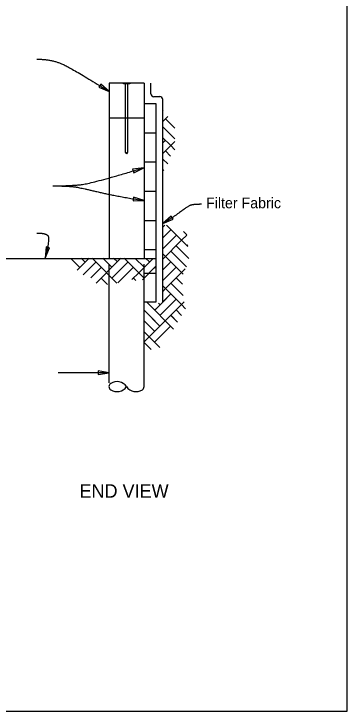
# Model space of a CAD drawing. Extents: x 10624 to 10731, y 76456 to 76513.
# Drawn here: x 10676.79 to 10686.28, y 76469.69 to 76489.57 of the extents above; entities that cross this region are included whole.
import ezdxf

# ---------------------------------------------------------------- set-up
doc = ezdxf.new("R2010")
doc.units = 0
for name, color, linetype in [('ActivePts-ConstElements', 7, 'Continuous'), ('Dimension', 7, 'Continuous'), ('GroundLines', 7, 'Continuous'), ('Miscellaneous', 7, 'Continuous'), ('Patterning', 7, 'Continuous'), ('SteelMisc', 7, 'Continuous'), ('SteelMisc_h', 7, 'Continuous'), ('TextStructures', 7, 'Continuous'), ('Wood', 7, 'Continuous'), ('Wood_h', 7, 'Continuous')]:
    doc.layers.add(name, color=color, linetype=linetype)

msp = doc.modelspace()

# ---------------------------------------------------------------- linework, layer by layer
at = {"layer": 'ActivePts-ConstElements'}
msp.add_lwpolyline([(10624.7, 76469.694), (10686.276, 76469.694), (10686.276, 76508.613), (10624.7, 76508.613)], close=True, dxfattribs=at)
at = {"layer": 'Dimension'}
msp.add_line((10679.5, 76479.339), (10678.045, 76479.339), dxfattribs=at)
for points in [[(10679.5, 76487.354), (10679.264, 76487.565), (10679.208, 76487.476)], [(10680.484, 76485.183), (10680.169, 76485.142), (10680.201, 76485.041)], [(10680.499, 76484.246), (10680.198, 76484.347), (10680.182, 76484.243)], [(10681.031, 76483.593), (10681.324, 76483.712), (10681.269, 76483.802)], [(10677.679, 76482.609), (10677.805, 76482.9), (10677.702, 76482.925)], [(10679.5, 76479.339), (10679.188, 76479.392), (10679.188, 76479.286)]]:
    msp.add_lwpolyline(points, close=True, dxfattribs=at)
msp.add_open_spline([(10677.442, 76483.32), (10677.726, 76483.32), (10677.808, 76483.134), (10677.679, 76482.609)], degree=2, dxfattribs=at)
at = {"layer": 'GroundLines'}
msp.add_line((10676.348, 76482.598), (10680.498, 76482.598), dxfattribs=at)
at = {"layer": 'Miscellaneous'}
for p, q in [((10680.689, 76487.292), (10680.689, 76487.598)), ((10680.772, 76487.209), (10680.943, 76487.209)), ((10681.026, 76481.348), (10681.026, 76487.126))]:
    msp.add_line(p, q, dxfattribs=at)
for centre, start, end in [((10680.772, 76487.292), 180, 270), ((10680.943, 76487.126), 0, 90)]:
    msp.add_arc(centre, 0.0833, start, end, dxfattribs=at)
at = {"layer": 'Patterning'}
for p, q in [((10681.03, 76486.805), (10681.015, 76486.79)), ((10681.03, 76486.805), (10681.015, 76486.79)), ((10681.03, 76486.805), (10681.015, 76486.79)), ((10681.17, 76486.646), (10681.018, 76486.494)), ((10681.17, 76486.646), (10681.018, 76486.494)), ((10681.17, 76486.646), (10681.018, 76486.494)), ((10681.104, 76486.58), (10681.371, 76486.313)), ((10681.104, 76486.58), (10681.371, 76486.313)), ((10681.104, 76486.58), (10681.371, 76486.313)), ((10681.02, 76486.359), (10681.371, 76486.008)), ((10681.02, 76486.359), (10681.371, 76486.008)), ((10681.02, 76486.359), (10681.371, 76486.008)), ((10681.254, 76485.813), (10681.024, 76486.043)), ((10681.254, 76485.813), (10681.024, 76486.043)), ((10681.254, 76485.813), (10681.024, 76486.043)), ((10681.101, 76485.966), (10681.025, 76485.89)), ((10681.101, 76485.966), (10681.025, 76485.89)), ((10681.101, 76485.966), (10681.025, 76485.89)), ((10681.254, 76485.813), (10681.029, 76485.588)), ((10681.254, 76485.813), (10681.029, 76485.588)), ((10681.254, 76485.813), (10681.029, 76485.588)), ((10681.371, 76485.93), (10681.254, 76485.813)), ((10681.371, 76485.93), (10681.254, 76485.813)), ((10681.371, 76485.93), (10681.254, 76485.813)), ((10681.371, 76485.696), (10681.254, 76485.813)), ((10681.371, 76485.696), (10681.254, 76485.813)), ((10681.371, 76485.696), (10681.254, 76485.813)), ((10681.251, 76485.517), (10681.104, 76485.663)), ((10681.251, 76485.517), (10681.104, 76485.663)), ((10681.251, 76485.517), (10681.104, 76485.663)), ((10681.171, 76485.291), (10681.031, 76485.431)), ((10681.171, 76485.291), (10681.031, 76485.431)), ((10681.171, 76485.291), (10681.031, 76485.431)), ((10681.054, 76485.102), (10681.034, 76485.122)), ((10681.054, 76485.102), (10681.034, 76485.122)), ((10681.054, 76485.102), (10681.034, 76485.122)), ((10681.085, 76483.545), (10681.025, 76483.485)), ((10681.085, 76483.545), (10681.025, 76483.485)), ((10681.085, 76483.545), (10681.025, 76483.485)), ((10681.261, 76483.416), (10681.025, 76483.18)), ((10681.261, 76483.416), (10681.025, 76483.18)), ((10681.261, 76483.416), (10681.025, 76483.18)), ((10681.565, 76483.115), (10681.135, 76483.545)), ((10681.565, 76483.115), (10681.135, 76483.545)), ((10681.565, 76483.115), (10681.135, 76483.545)), ((10681.414, 76483.263), (10681.025, 76482.875)), ((10681.414, 76483.263), (10681.025, 76482.875)), ((10681.414, 76483.263), (10681.025, 76482.875)), ((10681.715, 76483.265), (10681.565, 76483.115)), ((10681.715, 76483.265), (10681.565, 76483.115)), ((10681.715, 76483.265), (10681.565, 76483.115)), ((10681.714, 76483.271), (10681.622, 76483.363)), ((10681.714, 76483.271), (10681.622, 76483.363)), ((10681.714, 76483.271), (10681.622, 76483.363)), ((10681.563, 76483.114), (10681.025, 76482.576)), ((10681.563, 76483.114), (10681.025, 76482.576)), ((10681.563, 76483.114), (10681.025, 76482.576)), ((10681.563, 76483.114), (10681.744, 76482.933)), ((10681.563, 76483.114), (10681.744, 76482.933)), ((10681.563, 76483.114), (10681.744, 76482.933)), ((10681.74, 76482.984), (10681.718, 76482.963)), ((10681.74, 76482.984), (10681.718, 76482.963)), ((10681.74, 76482.984), (10681.718, 76482.963)), ((10681.258, 76482.808), (10681.703, 76482.362)), ((10681.258, 76482.808), (10681.703, 76482.362)), ((10681.258, 76482.808), (10681.703, 76482.362)), ((10681.41, 76482.961), (10681.773, 76482.598)), ((10681.41, 76482.961), (10681.773, 76482.598)), ((10681.41, 76482.961), (10681.773, 76482.598)), ((10678.409, 76482.597), (10678.665, 76482.34)), ((10678.409, 76482.597), (10678.665, 76482.34)), ((10678.409, 76482.597), (10678.665, 76482.34)), ((10678.93, 76482.605), (10678.59, 76482.265)), ((10678.93, 76482.605), (10678.59, 76482.265)), ((10678.93, 76482.605), (10678.59, 76482.265)), ((10678.705, 76482.606), (10678.818, 76482.493)), ((10678.705, 76482.606), (10678.818, 76482.493)), ((10678.705, 76482.606), (10678.818, 76482.493)), ((10679.428, 76482.192), (10679.015, 76482.605)), ((10679.428, 76482.192), (10679.015, 76482.605)), ((10679.428, 76482.192), (10679.015, 76482.605)), ((10679.58, 76482.345), (10679.322, 76482.603)), ((10679.58, 76482.345), (10679.322, 76482.603)), ((10679.58, 76482.345), (10679.322, 76482.603)), ((10679.837, 76482.601), (10679.428, 76482.192)), ((10679.837, 76482.601), (10679.428, 76482.192)), ((10679.837, 76482.601), (10679.428, 76482.192)), ((10679.733, 76482.498), (10679.628, 76482.602)), ((10679.733, 76482.498), (10679.628, 76482.602)), ((10679.733, 76482.498), (10679.628, 76482.602)), ((10680.341, 76482.189), (10679.929, 76482.601)), ((10680.341, 76482.189), (10679.929, 76482.601)), ((10680.341, 76482.189), (10679.929, 76482.601)), ((10680.242, 76482.6), (10680.497, 76482.345)), ((10680.242, 76482.6), (10680.497, 76482.345)), ((10680.242, 76482.6), (10680.497, 76482.345)), ((10680.75, 76482.598), (10680.341, 76482.189)), ((10680.75, 76482.598), (10680.341, 76482.189)), ((10680.75, 76482.598), (10680.341, 76482.189)), ((10680.498, 76482.598), (10680.832, 76482.598)), ((10680.548, 76482.599), (10680.649, 76482.498)), ((10680.548, 76482.599), (10680.649, 76482.498)), ((10680.548, 76482.599), (10680.649, 76482.498)), ((10681.56, 76482.194), (10681.025, 76482.729)), ((10681.56, 76482.194), (10681.025, 76482.729)), ((10681.56, 76482.194), (10681.025, 76482.729)), ((10679.123, 76482.493), (10678.762, 76482.131)), ((10679.123, 76482.493), (10678.762, 76482.131)), ((10679.123, 76482.493), (10678.762, 76482.131)), ((10680.035, 76482.495), (10679.58, 76482.039)), ((10680.035, 76482.495), (10679.58, 76482.039)), ((10680.035, 76482.495), (10679.58, 76482.039)), ((10681.255, 76482.5), (10681.025, 76482.27)), ((10681.255, 76482.5), (10681.025, 76482.27)), ((10681.255, 76482.5), (10681.025, 76482.27)), ((10679.276, 76482.34), (10678.981, 76482.044)), ((10679.276, 76482.34), (10678.981, 76482.044)), ((10679.276, 76482.34), (10678.981, 76482.044)), ((10679.426, 76482.19), (10679.127, 76481.892)), ((10679.426, 76482.19), (10679.127, 76481.892)), ((10679.426, 76482.19), (10679.127, 76481.892)), ((10679.426, 76482.19), (10679.723, 76481.893)), ((10679.426, 76482.19), (10679.723, 76481.893)), ((10679.426, 76482.19), (10679.723, 76481.893)), ((10680.188, 76482.342), (10679.744, 76481.898)), ((10680.188, 76482.342), (10679.744, 76481.898)), ((10680.188, 76482.342), (10679.744, 76481.898)), ((10680.341, 76482.189), (10680.144, 76481.992)), ((10680.341, 76482.189), (10680.144, 76481.992)), ((10680.341, 76482.189), (10680.144, 76481.992)), ((10680.493, 76482.037), (10680.341, 76482.189)), ((10680.417, 76482.113), (10680.341, 76482.189)), ((10680.417, 76482.113), (10680.341, 76482.189)), ((10680.832, 76482.374), (10680.447, 76481.99)), ((10680.832, 76482.374), (10680.779, 76482.322)), ((10680.832, 76482.374), (10680.779, 76482.322)), ((10681.407, 76482.347), (10681.026, 76481.965)), ((10681.407, 76482.347), (10681.026, 76481.965)), ((10681.407, 76482.347), (10681.026, 76481.965)), ((10681.56, 76482.194), (10681.105, 76481.739)), ((10681.56, 76482.194), (10681.105, 76481.739)), ((10681.56, 76482.194), (10681.105, 76481.739)), ((10681.667, 76482.301), (10681.56, 76482.194)), ((10681.667, 76482.301), (10681.56, 76482.194)), ((10681.667, 76482.301), (10681.56, 76482.194)), ((10681.609, 76482.146), (10681.56, 76482.194)), ((10681.609, 76482.146), (10681.56, 76482.194)), ((10681.609, 76482.146), (10681.56, 76482.194)), ((10679.273, 76482.038), (10679.455, 76481.856)), ((10679.273, 76482.038), (10679.455, 76481.856)), ((10679.273, 76482.038), (10679.455, 76481.856)), ((10680.259, 76481.972), (10680.191, 76482.039)), ((10680.22, 76482.01), (10680.191, 76482.039)), ((10680.22, 76482.01), (10680.191, 76482.039)), ((10681.591, 76481.863), (10681.411, 76482.044)), ((10681.591, 76481.863), (10681.411, 76482.044)), ((10681.591, 76481.863), (10681.411, 76482.044)), ((10681.026, 76481.815), (10681.103, 76481.737)), ((10681.026, 76481.815), (10681.103, 76481.737)), ((10681.026, 76481.815), (10681.103, 76481.737)), ((10681.609, 76481.54), (10681.258, 76481.892)), ((10681.609, 76481.54), (10681.258, 76481.892)), ((10681.609, 76481.54), (10681.258, 76481.892)), ((10681.103, 76481.737), (10681.026, 76481.659)), ((10681.103, 76481.737), (10681.026, 76481.659)), ((10681.103, 76481.737), (10681.026, 76481.659)), ((10681.56, 76481.284), (10681.105, 76481.739)), ((10681.56, 76481.284), (10681.105, 76481.739)), ((10681.56, 76481.284), (10681.105, 76481.739)), ((10681.256, 76481.584), (10680.808, 76481.136)), ((10681.409, 76481.432), (10680.948, 76480.97)), ((10681.256, 76481.584), (10681.026, 76481.354)), ((10681.256, 76481.584), (10681.026, 76481.354)), ((10681.334, 76480.584), (10680.58, 76481.338)), ((10681.558, 76481.282), (10680.637, 76480.36)), ((10680.905, 76481.324), (10680.948, 76481.281)), ((10681.558, 76481.282), (10681.678, 76481.163)), ((10681.558, 76481.282), (10681.678, 76481.163)), ((10681.558, 76481.282), (10681.678, 76481.163)), ((10681.641, 76481.364), (10681.56, 76481.284)), ((10681.641, 76481.364), (10681.56, 76481.284)), ((10681.641, 76481.364), (10681.56, 76481.284)), ((10680.948, 76480.671), (10680.51, 76481.109)), ((10680.824, 76481.153), (10680.795, 76481.123)), ((10680.824, 76481.153), (10680.795, 76481.123)), ((10680.824, 76481.153), (10680.795, 76481.123)), ((10681.406, 76481.129), (10681.564, 76480.971)), ((10681.406, 76481.129), (10681.564, 76480.971)), ((10681.406, 76481.129), (10681.564, 76480.971)), ((10680.803, 76480.51), (10680.487, 76480.826)), ((10680.948, 76480.671), (10680.689, 76480.93)), ((10681.253, 76480.976), (10681.45, 76480.779)), ((10681.253, 76480.976), (10681.45, 76480.779)), ((10681.256, 76480.974), (10681.45, 76480.779)), ((10681.25, 76480.668), (10680.869, 76480.287)), ((10681.25, 76480.668), (10681.083, 76480.501)), ((10681.25, 76480.668), (10681.083, 76480.501)), ((10680.5, 76480.504), (10680.945, 76480.059)), ((10680.64, 76480.364), (10680.494, 76480.218)), ((10680.495, 76480.204), (10680.698, 76480.001)), ((10680.64, 76480.364), (10680.64, 76480.364)), ((10680.908, 76480.326), (10680.795, 76480.213)), ((10680.908, 76480.326), (10680.795, 76480.213)), ((10680.908, 76480.326), (10680.795, 76480.213))]:
    msp.add_line(p, q, dxfattribs=at)
at = {"layer": 'SteelMisc'}
msp.add_lwpolyline([(10679.906, 76487.598), (10680.093, 76487.598), (10680.093, 76487.577), (10679.906, 76487.577)], close=True, dxfattribs=at)
at = {"layer": 'SteelMisc_h'}
for p, q in [((10679.968, 76485.631), (10679.968, 76487.577)), ((10680.031, 76485.631), (10680.031, 76487.577)), ((10679.999, 76485.577), (10679.968, 76485.631)), ((10679.999, 76485.577), (10680.031, 76485.631))]:
    msp.add_line(p, q, dxfattribs=at)
at = {"layer": 'TextStructures'}
for points in [[(10677.443, 76488.277), (10677.839, 76488.277), (10678.441, 76488.021), (10679.5, 76487.354)], [(10677.895, 76484.665), (10678.331, 76484.665), (10679.008, 76484.73), (10680.484, 76485.183)], [(10677.895, 76484.665), (10678.366, 76484.665), (10678.742, 76484.599), (10679.666, 76484.379), (10680.499, 76484.246)], [(10682.129, 76484.14), (10681.909, 76484.14), (10681.748, 76484.09), (10681.397, 76483.819), (10681.031, 76483.593)]]:
    msp.add_open_spline(points, degree=2, dxfattribs=at)
at = {"layer": 'Wood'}
for p, q in [((10679.5, 76487.598), (10679.5, 76482.598)), ((10680.498, 76487.598), (10679.5, 76487.598)), ((10680.498, 76487.598), (10680.498, 76482.598)), ((10680.498, 76486.598), (10679.5, 76486.598))]:
    msp.add_line(p, q, dxfattribs=at)
for points in [[(10680.498, 76487.014), (10680.832, 76487.014), (10680.832, 76486.181)], [(10680.498, 76486.181), (10680.832, 76486.181), (10680.832, 76485.348)], [(10680.498, 76485.348), (10680.832, 76485.348), (10680.832, 76484.514)], [(10680.498, 76484.514), (10680.832, 76484.514), (10680.832, 76483.681)], [(10680.498, 76483.681), (10680.832, 76483.681), (10680.832, 76482.848)], [(10680.498, 76482.848), (10680.832, 76482.848), (10680.832, 76482.598)]]:
    msp.add_lwpolyline(points, dxfattribs=at)
at = {"layer": 'Wood_h'}
for p, q in [((10679.5, 76479.05), (10679.5, 76482.431)), ((10680.495, 76478.944), (10680.495, 76482.431)), ((10680.832, 76481.348), (10680.495, 76481.348))]:
    msp.add_line(p, q, dxfattribs=at)
for points in [[(10680.832, 76482.598), (10680.832, 76482.181)], [(10680.498, 76482.181), (10680.832, 76482.181), (10680.832, 76481.348)]]:
    msp.add_lwpolyline(points, dxfattribs=at)
for centre, radius, start, end in [((10679.602, 76478.944), 0.107, 122.6152, 179.9979), ((10679.723, 76478.758), 0.329, 34.3251, 123.0426), ((10679.602, 76478.944), 0.107, 179.9979, 237.3848), ((10679.723, 76479.129), 0.329, 236.955, 325.6725), ((10680.266, 76479.129), 0.329, 214.3153, 303.0328), ((10680.388, 76478.944), 0.107, 302.6152, 0.0021)]:
    msp.add_arc(centre, radius, start, end, dxfattribs=at)

# ---------------------------------------------------------------- texts
at = {"layer": 'TextStructures'}
for s, height, p in [('Filter Fabric', 0.3024, (10682.26, 76484.028)), ('END VIEW', 0.384, (10678.655, 76475.776))]:
    msp.add_text(s, height=height, dxfattribs=at).set_placement(p)

doc.saveas('drawing.dxf')
